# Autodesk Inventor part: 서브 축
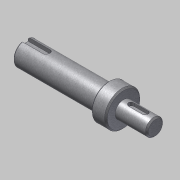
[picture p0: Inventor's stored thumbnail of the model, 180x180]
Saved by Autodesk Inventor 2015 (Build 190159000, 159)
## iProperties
Created: 2016-04
Part Number: 서브 축
Document SubType Name: Modeling
Designer: mdu
Density: 1 g/cm^3
Mass: 19.9624 g
Surface Area: 57.7178 cm^2
Volume: 19.9624 cm^3
Material: 강철, 연강
Appearance: 금속-강(스테인리스, 브러시됨)
Author: mdu
Revision Number: 1
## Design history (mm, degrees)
sketch "스케치1"
  geometry: L1 (-16.331, 0)-(-108.831, 0); L2 (-16.331, 0)-(-16.331, -6); L3 (-16.331, -6)-(-38.831, -6); L4 (-38.831, -12.5)-(-46.5, -12.5); L5 (-46.5, -8.5)-(-108.831, -8.5); L6 (-108.831, -8.5)-(-108.831, 0); L7 (-46.5, -8.5)-(-46.5, -12.5); L8 (-38.831, -6)-(-38.831, -12.5); L9 (-46.5, 12.249)-(-46.5, -12.249) reference; L10 (-38.831, -17)-(-38.831, 17) reference; 2 further points
  constraints: 17 end point, 4 perpendicular, 2 collinear, 2 parallel, 1 horizontal, 1 midpoint, 1 point on line
  dimensions: "d1" = 12 diameter of L3 L1; "d2" = 25 diameter of L4 L1; "d3" = 17 diameter of L5 L1; "d18" = 22.5 distance of L2.end L3.end; "d20" = 70 distance between parallel lines of L6 L8; "d21" = 7.66872 distance of L4.start L4.end (derived)
revolve "회전1" sketch "스케치1" stored, may be unused: angle "d5" = 90 deg
chamfer "모따기1" distance "d6" = 1; stored, may be unused: second distance "d7" = 2, angle "d8" = 45 deg
node "작업 평면1"
sketch "스케치2"
  geometry: L1 (11.25, 5)-(11.25, -5) reference; L2 (-5.75, -2)-(4.25, -2); L3 (4.25, 2)-(-5.75, 2); A1 r 2 centre (4.25, 0) between (4.25, -2) and (4.25, 2); A2 r 2 centre (-5.75, 0) between (-5.75, 2) and (-5.75, -2); 2 further points
  constraints: 4 end point, 4 point on circle, 4 tangent, 2 centre point, 1 horizontal alignment, 1 midpoint, 1 parallel, 1 perpendicular
  dimensions: "d9" = 4 distance between parallel lines of L2 L3; "d10" = 14 dimension on A1 A2; "d11" = 5 distance edge to line of A1 L1
extrude "돌출1" cut sketch "스케치2" distance "d12" = 2.5; taper "d13" = 0 deg
node "작업 평면2"
sketch "스케치3"
  geometry: L1 (-31.166, -7.5)-(-31.166, 7.5) reference; L2 (-31.166, 2.5)-(-15.666, 2.5); L3 (-15.666, -2.5)-(-31.166, -2.5); A1 r 2.5 centre (-15.666, 0) between (-15.666, -2.5) and (-15.666, 2.5); 2 further points
  constraints: 4 end point, 2 perpendicular, 2 point on circle, 2 point on line, 2 tangent, 1 centre point, 1 horizontal alignment, 1 midpoint
  dimensions: "d14" = 5 distance between parallel lines of L3 L2; "d15" = 18 dimension on A1 L1
extrude "돌출2" cut sketch "스케치3" distance "d16" = 3; taper "d17" = 0 deg
sketch "스케치4"
  geometry: C1 r 12.5 at (0, 0) reference; 1 further point
extrude "돌출3" join sketch "스케치4" distance "d22" = 3; taper "d23" = 0 deg
chamfer "모따기2" distance "d24" = 1; stored, may be unused: second distance "d25" = 2, angle "d26" = 45 deg
node "솔리드1"
node "참조4"
node "참조5"
